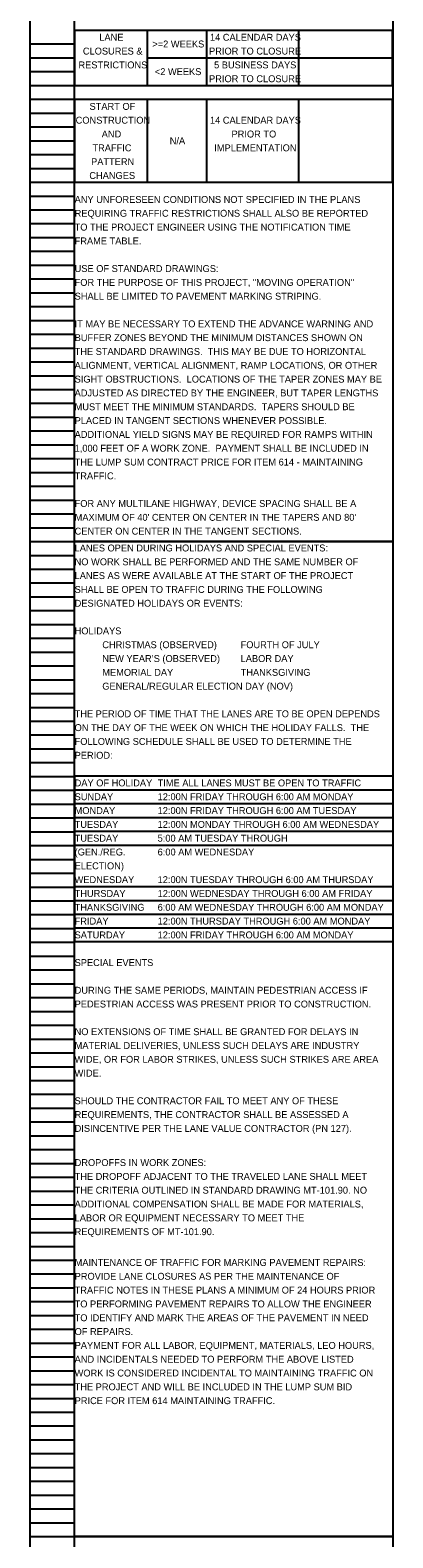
# Model space of a CAD drawing. Extents: x 16463 to 16500, y 5400 to 5823.
# Drawn here: x 16463.05 to 16470.39, y 5762.97 to 5793.51 of the extents above; entities that cross this region are included whole.
import ezdxf

# ---------------------------------------------------------------- set-up
doc = ezdxf.new("R2010")
doc.units = 0
for name, color, linetype in [('Default', 7, 'Continuous'), ('SC_Scratch1', 7, 'Continuous'), ('SH_Data', 7, 'Continuous')]:
    doc.layers.add(name, color=color, linetype=linetype)

msp = doc.modelspace()

# ---------------------------------------------------------------- linework, layer by layer
at = {"layer": 'Default'}
for p, q in [((16463.949, 5778.402), (16470.389, 5778.402)), ((16463.949, 5778.122), (16470.389, 5778.122)), ((16463.949, 5777.842), (16470.389, 5777.842)), ((16463.949, 5777.562), (16470.389, 5777.562)), ((16463.949, 5777.282), (16470.389, 5777.282)), ((16463.949, 5777.002), (16470.389, 5777.002)), ((16463.949, 5776.162), (16470.389, 5776.162)), ((16463.949, 5775.882), (16470.389, 5775.882)), ((16463.949, 5775.602), (16470.389, 5775.602)), ((16463.949, 5775.322), (16470.389, 5775.322))]:
    msp.add_line(p, q, dxfattribs=at)
for points in [[(16463.949, 5778.402), (16470.389, 5778.402), (16470.389, 5775.051)], [(16463.949, 5778.402), (16463.949, 5775.051), (16470.389, 5775.051)]]:
    msp.add_lwpolyline(points, dxfattribs=at)
at = {"layer": 'SC_Scratch1'}
for points in [[(16463.949, 5803.312), (16470.389, 5803.312), (16470.389, 5783.152), (16463.949, 5783.152)], [(16463.949, 5783.152), (16470.389, 5783.152), (16470.389, 5762.992), (16463.949, 5762.992)], [(16463.949, 5783.152), (16470.389, 5783.152), (16470.389, 5762.992), (16463.949, 5762.992)], [(16463.949, 5762.992), (16470.389, 5762.992), (16470.389, 5742.832), (16463.949, 5742.832)]]:
    msp.add_lwpolyline(points, close=True, dxfattribs=at)
at = {"layer": 'SH_Data'}
for p, q in [((16463.049, 5783.152), (16463.049, 5803.312)), ((16463.949, 5783.152), (16463.949, 5803.312)), ((16463.949, 5793.512), (16470.373, 5793.512)), ((16463.949, 5793.512), (16463.949, 5792.392)), ((16465.415, 5793.512), (16465.415, 5792.392)), ((16466.618, 5793.512), (16466.618, 5792.392)), ((16468.479, 5793.512), (16468.479, 5792.392)), ((16470.373, 5793.512), (16470.373, 5792.392)), ((16463.049, 5793.232), (16463.949, 5793.232)), ((16463.049, 5792.952), (16463.949, 5792.952)), ((16465.415, 5792.952), (16470.373, 5792.952)), ((16463.049, 5792.672), (16463.949, 5792.672)), ((16463.049, 5792.392), (16463.949, 5792.392)), ((16463.949, 5792.392), (16470.373, 5792.392)), ((16463.049, 5792.112), (16463.949, 5792.112)), ((16463.949, 5792.112), (16470.373, 5792.112)), ((16463.949, 5792.112), (16463.949, 5790.432)), ((16465.415, 5792.112), (16465.415, 5790.432)), ((16466.618, 5792.112), (16466.618, 5790.432)), ((16468.479, 5792.112), (16468.479, 5790.432)), ((16470.373, 5792.112), (16470.373, 5790.432)), ((16463.049, 5791.832), (16463.949, 5791.832)), ((16463.049, 5791.552), (16463.949, 5791.552)), ((16463.049, 5791.272), (16463.949, 5791.272)), ((16463.049, 5790.992), (16463.949, 5790.992)), ((16463.049, 5790.712), (16463.949, 5790.712)), ((16463.049, 5790.432), (16463.949, 5790.432)), ((16463.949, 5790.432), (16470.373, 5790.432)), ((16463.049, 5790.152), (16463.949, 5790.152)), ((16463.049, 5789.872), (16463.949, 5789.872)), ((16463.049, 5789.592), (16463.949, 5789.592)), ((16463.049, 5789.312), (16463.949, 5789.312)), ((16463.049, 5789.032), (16463.949, 5789.032)), ((16463.049, 5788.752), (16463.949, 5788.752)), ((16463.049, 5788.472), (16463.949, 5788.472)), ((16463.049, 5788.192), (16463.949, 5788.192)), ((16463.049, 5787.912), (16463.949, 5787.912)), ((16463.049, 5787.632), (16463.949, 5787.632)), ((16463.049, 5787.352), (16463.949, 5787.352)), ((16463.049, 5787.072), (16463.949, 5787.072)), ((16463.049, 5786.792), (16463.949, 5786.792)), ((16463.049, 5786.512), (16463.949, 5786.512)), ((16463.049, 5786.232), (16463.949, 5786.232)), ((16463.049, 5785.952), (16463.949, 5785.952)), ((16463.049, 5785.672), (16463.949, 5785.672)), ((16463.049, 5785.392), (16463.949, 5785.392)), ((16463.049, 5785.112), (16463.949, 5785.112)), ((16463.049, 5784.832), (16463.949, 5784.832)), ((16463.049, 5784.552), (16463.949, 5784.552)), ((16463.049, 5784.272), (16463.949, 5784.272)), ((16463.049, 5783.992), (16463.949, 5783.992)), ((16463.049, 5783.712), (16463.949, 5783.712)), ((16463.049, 5783.432), (16463.949, 5783.432)), ((16463.049, 5762.992), (16463.049, 5783.152)), ((16463.049, 5783.152), (16463.949, 5783.152)), ((16463.049, 5783.152), (16463.949, 5783.152)), ((16463.949, 5762.992), (16463.949, 5783.152)), ((16463.049, 5782.872), (16463.949, 5782.872)), ((16463.049, 5782.592), (16463.949, 5782.592)), ((16463.049, 5782.312), (16463.949, 5782.312)), ((16463.049, 5782.032), (16463.949, 5782.032)), ((16463.049, 5781.752), (16463.949, 5781.752)), ((16463.049, 5781.472), (16463.949, 5781.472)), ((16463.049, 5781.192), (16463.949, 5781.192)), ((16463.049, 5780.912), (16463.949, 5780.912)), ((16463.049, 5780.632), (16463.949, 5780.632)), ((16463.049, 5780.352), (16463.949, 5780.352)), ((16463.049, 5780.072), (16463.949, 5780.072)), ((16463.049, 5779.792), (16463.949, 5779.792)), ((16463.049, 5779.512), (16463.949, 5779.512)), ((16463.049, 5779.232), (16463.949, 5779.232)), ((16463.049, 5778.952), (16463.949, 5778.952)), ((16463.049, 5778.672), (16463.949, 5778.672)), ((16463.049, 5778.392), (16463.949, 5778.392)), ((16463.049, 5778.112), (16463.949, 5778.112)), ((16463.049, 5777.832), (16463.949, 5777.832)), ((16463.049, 5777.552), (16463.949, 5777.552)), ((16463.049, 5777.272), (16463.949, 5777.272)), ((16463.049, 5776.992), (16463.949, 5776.992)), ((16463.049, 5776.712), (16463.949, 5776.712)), ((16463.049, 5776.432), (16463.949, 5776.432)), ((16463.049, 5776.152), (16463.949, 5776.152)), ((16463.049, 5775.872), (16463.949, 5775.872)), ((16463.049, 5775.592), (16463.949, 5775.592)), ((16463.049, 5775.312), (16463.949, 5775.312)), ((16463.049, 5775.032), (16463.949, 5775.032)), ((16463.049, 5774.752), (16463.949, 5774.752)), ((16463.049, 5774.472), (16463.949, 5774.472)), ((16463.049, 5774.192), (16463.949, 5774.192)), ((16463.049, 5773.912), (16463.949, 5773.912)), ((16463.049, 5773.632), (16463.949, 5773.632)), ((16463.049, 5773.352), (16463.949, 5773.352)), ((16463.049, 5773.072), (16463.949, 5773.072)), ((16463.049, 5772.792), (16463.949, 5772.792)), ((16463.049, 5772.512), (16463.949, 5772.512)), ((16463.049, 5772.232), (16463.949, 5772.232)), ((16463.049, 5771.952), (16463.949, 5771.952)), ((16463.049, 5771.672), (16463.949, 5771.672)), ((16463.049, 5771.392), (16463.949, 5771.392)), ((16463.049, 5771.112), (16463.949, 5771.112)), ((16463.049, 5770.832), (16463.949, 5770.832)), ((16463.049, 5770.552), (16463.949, 5770.552)), ((16463.049, 5770.272), (16463.949, 5770.272)), ((16463.049, 5769.992), (16463.949, 5769.992)), ((16463.049, 5769.712), (16463.949, 5769.712)), ((16463.049, 5769.432), (16463.949, 5769.432)), ((16463.049, 5769.152), (16463.949, 5769.152)), ((16463.049, 5768.872), (16463.949, 5768.872)), ((16463.049, 5768.592), (16463.949, 5768.592)), ((16463.049, 5768.312), (16463.949, 5768.312)), ((16463.049, 5768.032), (16463.949, 5768.032)), ((16463.049, 5767.752), (16463.949, 5767.752)), ((16463.049, 5767.472), (16463.949, 5767.472)), ((16463.049, 5767.192), (16463.949, 5767.192)), ((16463.049, 5766.912), (16463.949, 5766.912)), ((16463.049, 5766.632), (16463.949, 5766.632)), ((16463.049, 5766.352), (16463.949, 5766.352)), ((16463.049, 5766.072), (16463.949, 5766.072)), ((16463.049, 5765.792), (16463.949, 5765.792)), ((16463.049, 5765.512), (16463.949, 5765.512)), ((16463.049, 5765.232), (16463.949, 5765.232)), ((16463.049, 5764.952), (16463.949, 5764.952)), ((16463.049, 5764.672), (16463.949, 5764.672)), ((16463.049, 5764.392), (16463.949, 5764.392)), ((16463.049, 5764.112), (16463.949, 5764.112)), ((16463.049, 5763.832), (16463.949, 5763.832)), ((16463.049, 5763.552), (16463.949, 5763.552)), ((16463.049, 5763.272), (16463.949, 5763.272)), ((16463.049, 5742.832), (16463.049, 5762.992)), ((16463.049, 5762.992), (16463.949, 5762.992)), ((16463.049, 5762.992), (16463.949, 5762.992)), ((16463.949, 5742.832), (16463.949, 5762.992))]:
    msp.add_line(p, q, dxfattribs=at)

# ---------------------------------------------------------------- texts
at = {"layer": 'Default'}
for s, p in [('ANY UNFORESEEN CONDITIONS NOT SPECIFIED IN THE PLANS ', (16463.949, 5790.012)), ('REQUIRING TRAFFIC RESTRICTIONS SHALL ALSO BE REPORTED ', (16463.949, 5789.732)), ('TO THE PROJECT ENGINEER USING THE NOTIFICATION TIME ', (16463.949, 5789.452)), ('FRAME TABLE. ', (16463.949, 5789.172)), ('USE OF STANDARD DRAWINGS:', (16463.949, 5788.612)), ('FOR THE PURPOSE OF THIS PROJECT, "MOVING OPERATION" ', (16463.949, 5788.332)), ('SHALL BE LIMITED TO PAVEMENT MARKING STRIPING.', (16463.949, 5788.052)), ('IT MAY BE NECESSARY TO EXTEND THE ADVANCE WARNING AND ', (16463.949, 5787.492)), ('THE STANDARD DRAWINGS.  THIS MAY BE DUE TO HORIZONTAL ', (16463.949, 5786.932)), ('BUFFER ZONES BEYOND THE MINIMUM DISTANCES SHOWN ON ', (16463.949, 5787.212)), ('ALIGNMENT, VERTICAL ALIGNMENT, RAMP LOCATIONS, OR OTHER ', (16463.949, 5786.652)), ('SIGHT OBSTRUCTIONS.  LOCATIONS OF THE TAPER ZONES MAY BE ', (16463.949, 5786.372)), ('ADJUSTED AS DIRECTED BY THE ENGINEER, BUT TAPER LENGTHS ', (16463.949, 5786.092)), ('MUST MEET THE MINIMUM STANDARDS.  TAPERS SHOULD BE ', (16463.949, 5785.812)), ('PLACED IN TANGENT SECTIONS WHENEVER POSSIBLE.  ', (16463.949, 5785.532)), ('ADDITIONAL YIELD SIGNS MAY BE REQUIRED FOR RAMPS WITHIN ', (16463.949, 5785.252)), ('1,000 FEET OF A WORK ZONE.  PAYMENT SHALL BE INCLUDED IN ', (16463.949, 5784.972)), ('THE LUMP SUM CONTRACT PRICE FOR ITEM 614 - MAINTAINING ', (16463.949, 5784.692)), ('TRAFFIC.', (16463.949, 5784.412)), ('FOR ANY MULTILANE HIGHWAY, DEVICE SPACING SHALL BE A ', (16463.949, 5783.852)), ("MAXIMUM OF 40' CENTER ON CENTER IN THE TAPERS AND 80' ", (16463.949, 5783.572)), ('CENTER ON CENTER IN THE TANGENT SECTIONS.', (16463.949, 5783.292)), ('LANES OPEN DURING HOLIDAYS AND SPECIAL EVENTS:', (16463.949, 5782.951)), ('NO WORK SHALL BE PERFORMED AND THE SAME NUMBER OF ', (16463.949, 5782.671)), ('LANES AS WERE AVAILABLE AT THE START OF THE PROJECT ', (16463.949, 5782.391)), ('SHALL BE OPEN TO TRAFFIC DURING THE FOLLOWING ', (16463.949, 5782.111)), ('DESIGNATED HOLIDAYS OR EVENTS:', (16463.949, 5781.831)), ('HOLIDAYS', (16463.949, 5781.271)), ('CHRISTMAS (OBSERVED)', (16464.509, 5780.991)), ('FOURTH OF JULY', (16467.309, 5780.991)), ('NEW YEAR’S (OBSERVED)', (16464.509, 5780.711)), ('LABOR DAY', (16467.309, 5780.711)), ('MEMORIAL DAY          ', (16464.509, 5780.431)), ('THANKSGIVING', (16467.309, 5780.431)), ('GENERAL/REGULAR ELECTION DAY (NOV)', (16464.509, 5780.151)), ('THE PERIOD OF TIME THAT THE LANES ARE TO BE OPEN DEPENDS ', (16463.949, 5779.591)), ('ON THE DAY OF THE WEEK ON WHICH THE HOLIDAY FALLS.  THE ', (16463.949, 5779.311)), ('FOLLOWING SCHEDULE SHALL BE USED TO DETERMINE THE ', (16463.949, 5779.031)), ('PERIOD:', (16463.949, 5778.751)), ('DAY OF HOLIDAY', (16463.949, 5778.191)), ('TIME ALL LANES MUST BE OPEN TO TRAFFIC', (16465.629, 5778.191)), ('SUNDAY', (16463.949, 5777.911)), ('12:00N FRIDAY THROUGH 6:00 AM MONDAY', (16465.629, 5777.911)), ('MONDAY', (16463.949, 5777.631)), ('12:00N FRIDAY THROUGH 6:00 AM TUESDAY', (16465.629, 5777.631)), ('TUESDAY', (16463.949, 5777.351)), ('12:00N MONDAY THROUGH 6:00 AM WEDNESDAY', (16465.629, 5777.351)), ('TUESDAY', (16463.949, 5777.071)), ('5:00 AM TUESDAY THROUGH  ', (16465.629, 5777.071)), ('(GEN./REG.', (16463.949, 5776.791)), ('6:00 AM WEDNESDAY', (16465.629, 5776.791)), ('ELECTION)', (16463.949, 5776.511)), ('WEDNESDAY', (16463.949, 5776.231)), ('THURSDAY', (16463.949, 5775.951)), ('12:00N TUESDAY THROUGH 6:00 AM THURSDAY', (16465.629, 5776.231)), ('12:00N WEDNESDAY THROUGH 6:00 AM FRIDAY', (16465.629, 5775.951)), ('THANKSGIVING', (16463.949, 5775.671)), ('6:00 AM WEDNESDAY THROUGH 6:00 AM MONDAY', (16465.629, 5775.671)), ('FRIDAY', (16463.949, 5775.391)), ('12:00N THURSDAY THROUGH 6:00 AM MONDAY', (16465.629, 5775.391)), ('SATURDAY', (16463.949, 5775.111)), ('12:00N FRIDAY THROUGH 6:00 AM MONDAY', (16465.629, 5775.111)), ('SPECIAL EVENTS', (16463.949, 5774.551)), ('DURING THE SAME PERIODS, MAINTAIN PEDESTRIAN ACCESS IF ', (16463.949, 5773.991)), ('PEDESTRIAN ACCESS WAS PRESENT PRIOR TO CONSTRUCTION.', (16463.949, 5773.711)), ('NO EXTENSIONS OF TIME SHALL BE GRANTED FOR DELAYS IN ', (16463.949, 5773.151)), ('WIDE, OR FOR LABOR STRIKES, UNLESS SUCH STRIKES ARE AREA ', (16463.949, 5772.591)), ('MATERIAL DELIVERIES, UNLESS SUCH DELAYS ARE INDUSTRY ', (16463.949, 5772.871)), ('WIDE.', (16463.949, 5772.311)), ('SHOULD THE CONTRACTOR FAIL TO MEET ANY OF THESE ', (16463.949, 5771.751)), ('REQUIREMENTS, THE CONTRACTOR SHALL BE ASSESSED A ', (16463.949, 5771.471)), ('DISINCENTIVE PER THE LANE VALUE CONTRACTOR (PN 127).', (16463.949, 5771.191)), ('DROPOFFS IN WORK ZONES:', (16463.949, 5770.499)), ('THE DROPOFF ADJACENT TO THE TRAVELED LANE SHALL MEET ', (16463.949, 5770.219)), ('THE CRITERIA OUTLINED IN STANDARD DRAWING MT-101.90. NO ', (16463.949, 5769.939)), ('ADDITIONAL COMPENSATION SHALL BE MADE FOR MATERIALS, ', (16463.949, 5769.659)), ('LABOR OR EQUIPMENT NECESSARY TO MEET THE ', (16463.949, 5769.379)), ('REQUIREMENTS OF MT-101.90.', (16463.949, 5769.099)), ('MAINTENANCE OF TRAFFIC FOR MARKING PAVEMENT REPAIRS:', (16463.949, 5768.475)), ('PROVIDE LANE CLOSURES AS PER THE MAINTENANCE OF ', (16463.949, 5768.195)), ('TRAFFIC NOTES IN THESE PLANS A MINIMUM OF 24 HOURS PRIOR ', (16463.949, 5767.915)), ('TO PERFORMING PAVEMENT REPAIRS TO ALLOW THE ENGINEER ', (16463.949, 5767.635)), ('TO IDENTIFY AND MARK THE AREAS OF THE PAVEMENT IN NEED ', (16463.949, 5767.355)), ('OF REPAIRS.', (16463.949, 5767.075)), ('PAYMENT FOR ALL LABOR, EQUIPMENT, MATERIALS, LEO HOURS, ', (16463.949, 5766.795)), ('AND INCIDENTALS NEEDED TO PERFORM THE ABOVE LISTED ', (16463.949, 5766.515)), ('WORK IS CONSIDERED INCIDENTAL TO MAINTAINING TRAFFIC ON ', (16463.949, 5766.235)), ('THE PROJECT AND WILL BE INCLUDED IN THE LUMP SUM BID ', (16463.949, 5765.955)), ('PRICE FOR ITEM 614 MAINTAINING TRAFFIC.', (16463.949, 5765.675))]:
    msp.add_text(s, height=0.14, dxfattribs=at).set_placement(p)
at = {"layer": 'SH_Data'}
for s, p in [('LANE', (16464.448, 5793.298)), ('>=2 WEEKS', (16465.522, 5793.162)), ('14 CALENDAR DAYS', (16466.688, 5793.298)), ('RESTRICTIONS', (16464.027, 5792.738)), ('CLOSURES &', (16464.116, 5793.018)), ('PRIOR TO CLOSURE', (16466.67, 5793.018)), ('5 BUSINESS DAYS', (16466.772, 5792.738)), ('<2 WEEKS', (16465.573, 5792.602)), ('PRIOR TO CLOSURE', (16466.67, 5792.458)), ('START OF', (16464.251, 5791.898)), ('CONSTRUCTION', (16463.97, 5791.618)), ('14 CALENDAR DAYS', (16466.688, 5791.618)), ('AND', (16464.497, 5791.338)), ('N/A', (16465.874, 5791.202)), ('PRIOR TO', (16467.125, 5791.338)), ('TRAFFIC', (16464.31, 5791.058)), ('IMPLEMENTATION', (16466.776, 5791.058)), ('PATTERN', (16464.282, 5790.778)), ('CHANGES', (16464.247, 5790.498))]:
    msp.add_text(s, height=0.14, dxfattribs=at).set_placement(p)

doc.saveas('drawing.dxf')
